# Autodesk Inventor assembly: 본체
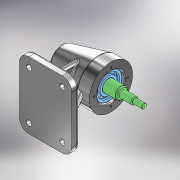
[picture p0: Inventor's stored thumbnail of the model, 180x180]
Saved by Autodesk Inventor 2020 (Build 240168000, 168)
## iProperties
Created: 2024-12
Part Number: 본체
Document SubType Name: Assembly
Designer: 1강의실14
Author: 1강의실14
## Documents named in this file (5)
- C:\Users\1강의실14\Desktop\741204V1001\본체.iam
- C:\Users\1강의실14\Desktop\741204V1001\본체.ipt
- C:\Users\1강의실14\Desktop\741204V1001\앵귤러 볼 베어링 7003A.ipt
- C:\Users\1강의실14\Desktop\741204V1001\앵귤러 볼 제어링 7204A.ipt
- C:\Users\1강의실14\Desktop\741204V1001\축.ipt
